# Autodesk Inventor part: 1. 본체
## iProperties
Created: 2014-11
Part Number: 1. 본체
Document SubType Name: Modeling
Designer: elite
Density: 2.71 g/cm^3
Material: 알루미늄-6061
Mass: 2834.32 g
Surface Area: 2062.54 cm^2
Volume: 1045.87 cm^3
Author: elite
